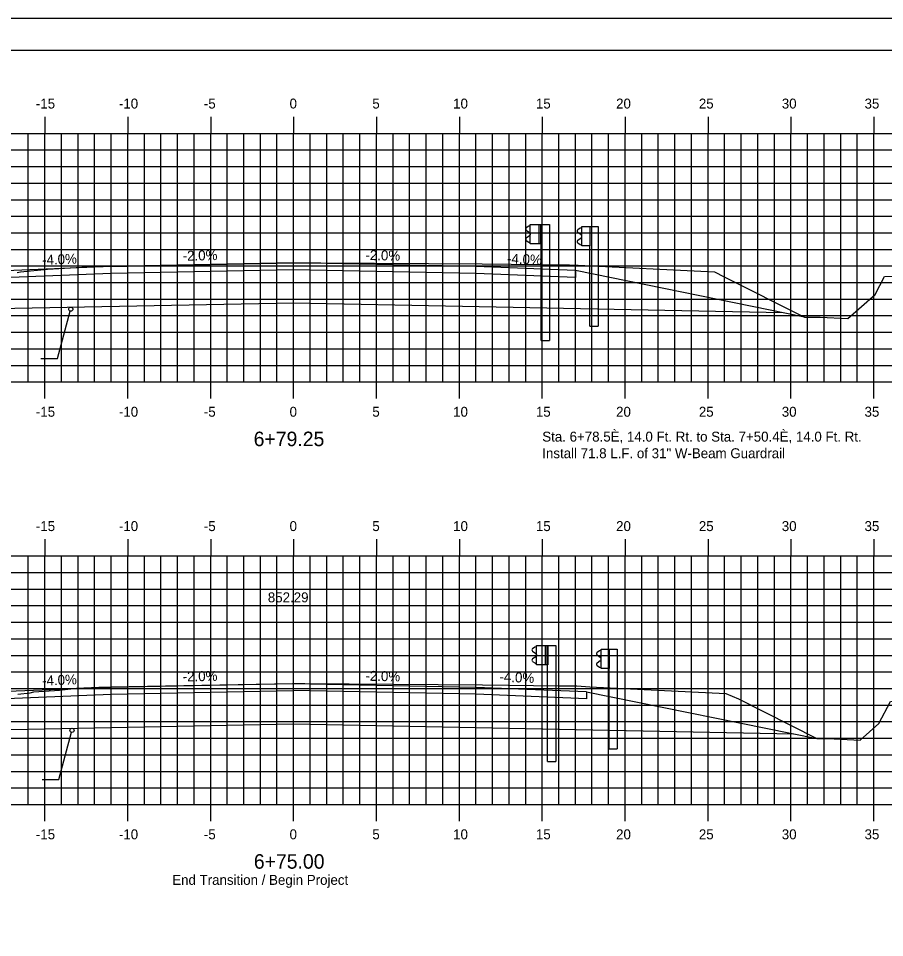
# Model space of a CAD drawing. Extents: x 2193811 to 2194294, y 863888 to 863998.
# Drawn here: x 2194016.6 to 2194068.9, y 863942.9 to 863998.4 of the extents above; entities that cross this region are included whole.
import ezdxf

# ---------------------------------------------------------------- set-up
doc = ezdxf.new("R2010")
doc.units = 0
for name, color, linetype in [('ANNOTATION', 7, 'Continuous'), ('BORDER', 7, 'Continuous'), ('D_Guardrail_Beam_Lt', 7, 'Continuous'), ('H_V ANNOTATION', 7, 'Continuous'), ('MAJOR', 7, 'Continuous'), ('MINOR', 7, 'Continuous'), ('PLOT BOUNDARY', 7, 'Continuous'), ('S_Guardrail_Beam', 7, 'Continuous'), ('S_Roadway_Centerline', 7, 'Continuous'), ('S_Utilities_Pole_Power', 7, 'Continuous'), ('TEMPLATE', 7, 'Continuous')]:
    doc.layers.add(name, color=color, linetype=linetype)

msp = doc.modelspace()

# ---------------------------------------------------------------- linework, layer by layer
at = {"layer": 'ANNOTATION'}
for points in [[(2194017.995, 863977.865), (2194018.995, 863977.865), (2194019.759, 863980.719)], [(2194018.072, 863952.447), (2194019.072, 863952.447), (2194019.836, 863955.301)]]:
    msp.add_lwpolyline(points, dxfattribs=at)
at = {"layer": 'BORDER'}
msp.add_lwpolyline([(2193958.23, 863891.446), (2194118.23, 863891.446), (2194118.23, 863996.446), (2193958.23, 863996.446)], close=True, dxfattribs=at)
at = {"layer": 'D_Guardrail_Beam_Lt'}
for p, q in [((2194047.5, 863985.869), (2194047.426, 863985.855)), ((2194047.5, 863985.952), (2194048.188, 863985.952)), ((2194047.5, 863984.786), (2194047.5, 863985.952)), ((2194048.021, 863985.952), (2194048.021, 863984.786)), ((2194048.125, 863985.952), (2194048.125, 863984.786)), ((2194048.188, 863985.952), (2194048.659, 863985.952)), ((2194048.188, 863985.952), (2194048.188, 863984.786)), ((2194048.659, 863985.952), (2194048.659, 863978.952)), ((2194047.411, 863985.848), (2194047.267, 863985.748)), ((2194047.267, 863985.605), (2194047.462, 863985.469)), ((2194047.496, 863985.404), (2194047.496, 863985.334)), ((2194047.462, 863985.27), (2194047.267, 863985.133)), ((2194047.267, 863984.99), (2194047.411, 863984.89)), ((2194047.426, 863984.884), (2194047.5, 863984.869)), ((2194048.188, 863984.786), (2194047.5, 863984.786)), ((2194048.167, 863978.952), (2194048.167, 863984.786)), ((2194048.167, 863978.952), (2194048.659, 863978.952)), ((2194047.791, 863960.443), (2194047.647, 863960.343)), ((2194047.88, 863960.464), (2194047.806, 863960.449)), ((2194047.88, 863960.547), (2194048.568, 863960.547)), ((2194047.88, 863959.381), (2194047.88, 863960.547)), ((2194048.401, 863960.547), (2194048.401, 863959.381)), ((2194048.505, 863960.547), (2194048.505, 863959.381)), ((2194048.568, 863960.547), (2194049.039, 863960.547)), ((2194048.568, 863960.547), (2194048.568, 863959.381)), ((2194049.039, 863960.547), (2194049.039, 863953.547)), ((2194047.647, 863960.2), (2194047.842, 863960.063)), ((2194047.842, 863959.864), (2194047.647, 863959.728)), ((2194047.876, 863959.999), (2194047.876, 863959.929)), ((2194047.647, 863959.585), (2194047.791, 863959.485)), ((2194047.806, 863959.478), (2194047.88, 863959.464)), ((2194048.568, 863959.381), (2194047.88, 863959.381)), ((2194048.547, 863953.547), (2194048.547, 863959.381)), ((2194048.547, 863953.547), (2194049.039, 863953.547))]:
    msp.add_line(p, q, dxfattribs=at)
for centre, major_axis, start_param, end_param in [((2194047.434, 863985.814), (-0.0417, 0), 4.907132, 5.323254), ((2194047.317, 863985.676), (-0.0877, 0), 5.323254, 7.243116), ((2194047.417, 863985.404), (0.0789, 0), 0, 0.959931), ((2194047.417, 863985.334), (0.0789, 0), 5.323254, 6.283185), ((2194047.317, 863985.062), (-0.0877, 0), 5.323254, 7.243116), ((2194047.434, 863984.924), (-0.0417, 0), 0.959931, 1.376053), ((2194047.697, 863960.271), (-0.0877, 0), 5.323254, 7.243116), ((2194047.814, 863960.409), (-0.0417, 0), 4.907132, 5.323254), ((2194047.797, 863959.999), (0.0789, 0), 0, 0.959931), ((2194047.797, 863959.929), (0.0789, 0), 5.323254, 6.283185), ((2194047.697, 863959.657), (-0.0877, 0), 5.323254, 7.243116), ((2194047.814, 863959.519), (-0.0417, 0), 0.959931, 1.376053)]:
    msp.add_ellipse(centre, major_axis=major_axis, ratio=0.995501, start_param=start_param, end_param=end_param, dxfattribs=at)
at = {"layer": 'MAJOR'}
for p, q in [((2194018.23, 863992.448), (2194018.23, 863991.446)), ((2194023.23, 863992.448), (2194023.23, 863991.446)), ((2194028.23, 863992.448), (2194028.23, 863991.446)), ((2194033.23, 863992.448), (2194033.23, 863991.446)), ((2194038.23, 863992.448), (2194038.23, 863991.446)), ((2194043.23, 863992.448), (2194043.23, 863991.446)), ((2194048.23, 863992.448), (2194048.23, 863991.446)), ((2194053.23, 863992.448), (2194053.23, 863991.446)), ((2194058.23, 863992.448), (2194058.23, 863991.446)), ((2194063.23, 863992.448), (2194063.23, 863991.446)), ((2194068.23, 863992.448), (2194068.23, 863991.446)), ((2193963.23, 863991.446), (2194103.23, 863991.446)), ((2193963.23, 863991.446), (2194103.23, 863991.446)), ((2194018.23, 863976.446), (2194018.23, 863991.446)), ((2194023.23, 863976.446), (2194023.23, 863991.446)), ((2194028.23, 863976.446), (2194028.23, 863991.446)), ((2194033.23, 863976.446), (2194033.23, 863991.446)), ((2194038.23, 863976.446), (2194038.23, 863991.446)), ((2194043.23, 863976.446), (2194043.23, 863991.446)), ((2194048.23, 863976.446), (2194048.23, 863991.446)), ((2194053.23, 863976.446), (2194053.23, 863991.446)), ((2194058.23, 863976.446), (2194058.23, 863991.446)), ((2194063.23, 863976.446), (2194063.23, 863991.446)), ((2194068.23, 863976.446), (2194068.23, 863991.446)), ((2193963.23, 863986.446), (2194103.23, 863986.446)), ((2193963.23, 863981.446), (2194103.23, 863981.446)), ((2193963.23, 863976.446), (2194103.23, 863976.446)), ((2194018.23, 863975.444), (2194018.23, 863976.446)), ((2194023.23, 863975.444), (2194023.23, 863976.446)), ((2194028.23, 863975.444), (2194028.23, 863976.446)), ((2194033.23, 863975.444), (2194033.23, 863976.446)), ((2194038.23, 863975.444), (2194038.23, 863976.446)), ((2194043.23, 863975.444), (2194043.23, 863976.446)), ((2194048.23, 863975.444), (2194048.23, 863976.446)), ((2194053.23, 863975.444), (2194053.23, 863976.446)), ((2194058.23, 863975.444), (2194058.23, 863976.446)), ((2194063.23, 863975.444), (2194063.23, 863976.446)), ((2194068.23, 863975.444), (2194068.23, 863976.446)), ((2194018.23, 863966.948), (2194018.23, 863965.946)), ((2194023.23, 863966.948), (2194023.23, 863965.946)), ((2194028.23, 863966.948), (2194028.23, 863965.946)), ((2194033.23, 863966.948), (2194033.23, 863965.946)), ((2194038.23, 863966.948), (2194038.23, 863965.946)), ((2194043.23, 863966.948), (2194043.23, 863965.946)), ((2194048.23, 863966.948), (2194048.23, 863965.946)), ((2194053.23, 863966.948), (2194053.23, 863965.946)), ((2194058.23, 863966.948), (2194058.23, 863965.946)), ((2194063.23, 863966.948), (2194063.23, 863965.946)), ((2194068.23, 863966.948), (2194068.23, 863965.946)), ((2193963.23, 863965.946), (2194103.23, 863965.946)), ((2193963.23, 863965.946), (2194103.23, 863965.946)), ((2194018.23, 863950.946), (2194018.23, 863965.946)), ((2194023.23, 863950.946), (2194023.23, 863965.946)), ((2194028.23, 863950.946), (2194028.23, 863965.946)), ((2194033.23, 863950.946), (2194033.23, 863965.946)), ((2194038.23, 863950.946), (2194038.23, 863965.946)), ((2194043.23, 863950.946), (2194043.23, 863965.946)), ((2194048.23, 863950.946), (2194048.23, 863965.946)), ((2194053.23, 863950.946), (2194053.23, 863965.946)), ((2194058.23, 863950.946), (2194058.23, 863965.946)), ((2194063.23, 863950.946), (2194063.23, 863965.946)), ((2194068.23, 863950.946), (2194068.23, 863965.946)), ((2193963.23, 863960.946), (2194103.23, 863960.946)), ((2193963.23, 863955.946), (2194103.23, 863955.946)), ((2193963.23, 863950.946), (2194103.23, 863950.946)), ((2194018.23, 863949.944), (2194018.23, 863950.946)), ((2194023.23, 863949.944), (2194023.23, 863950.946)), ((2194028.23, 863949.944), (2194028.23, 863950.946)), ((2194033.23, 863949.944), (2194033.23, 863950.946)), ((2194038.23, 863949.944), (2194038.23, 863950.946)), ((2194043.23, 863949.944), (2194043.23, 863950.946)), ((2194048.23, 863949.944), (2194048.23, 863950.946)), ((2194053.23, 863949.944), (2194053.23, 863950.946)), ((2194058.23, 863949.944), (2194058.23, 863950.946)), ((2194063.23, 863949.944), (2194063.23, 863950.946)), ((2194068.23, 863949.944), (2194068.23, 863950.946))]:
    msp.add_line(p, q, dxfattribs=at)
at = {"layer": 'MINOR'}
for p, q in [((2194017.23, 863976.446), (2194017.23, 863991.446)), ((2194019.23, 863976.446), (2194019.23, 863991.446)), ((2194020.23, 863976.446), (2194020.23, 863991.446)), ((2194021.23, 863976.446), (2194021.23, 863991.446)), ((2194022.23, 863976.446), (2194022.23, 863991.446)), ((2194024.23, 863976.446), (2194024.23, 863991.446)), ((2194025.23, 863976.446), (2194025.23, 863991.446)), ((2194026.23, 863976.446), (2194026.23, 863991.446)), ((2194027.23, 863976.446), (2194027.23, 863991.446)), ((2194029.23, 863976.446), (2194029.23, 863991.446)), ((2194030.23, 863976.446), (2194030.23, 863991.446)), ((2194031.23, 863976.446), (2194031.23, 863991.446)), ((2194032.23, 863976.446), (2194032.23, 863991.446)), ((2194034.23, 863976.446), (2194034.23, 863991.446)), ((2194035.23, 863976.446), (2194035.23, 863991.446)), ((2194036.23, 863976.446), (2194036.23, 863991.446)), ((2194037.23, 863976.446), (2194037.23, 863991.446)), ((2194039.23, 863976.446), (2194039.23, 863991.446)), ((2194040.23, 863976.446), (2194040.23, 863991.446)), ((2194041.23, 863976.446), (2194041.23, 863991.446)), ((2194042.23, 863976.446), (2194042.23, 863991.446)), ((2194044.23, 863976.446), (2194044.23, 863991.446)), ((2194045.23, 863976.446), (2194045.23, 863991.446)), ((2194046.23, 863976.446), (2194046.23, 863991.446)), ((2194047.23, 863976.446), (2194047.23, 863991.446)), ((2194049.23, 863976.446), (2194049.23, 863991.446)), ((2194050.23, 863976.446), (2194050.23, 863991.446)), ((2194051.23, 863976.446), (2194051.23, 863991.446)), ((2194052.23, 863976.446), (2194052.23, 863991.446)), ((2194054.23, 863976.446), (2194054.23, 863991.446)), ((2194055.23, 863976.446), (2194055.23, 863991.446)), ((2194056.23, 863976.446), (2194056.23, 863991.446)), ((2194057.23, 863976.446), (2194057.23, 863991.446)), ((2194059.23, 863976.446), (2194059.23, 863991.446)), ((2194060.23, 863976.446), (2194060.23, 863991.446)), ((2194061.23, 863976.446), (2194061.23, 863991.446)), ((2194062.23, 863976.446), (2194062.23, 863991.446)), ((2194064.23, 863976.446), (2194064.23, 863991.446)), ((2194065.23, 863976.446), (2194065.23, 863991.446)), ((2194066.23, 863976.446), (2194066.23, 863991.446)), ((2194067.23, 863976.446), (2194067.23, 863991.446)), ((2193963.23, 863990.446), (2194103.23, 863990.446)), ((2193963.23, 863989.446), (2194103.23, 863989.446)), ((2193963.23, 863988.446), (2194103.23, 863988.446)), ((2193963.23, 863987.446), (2194103.23, 863987.446)), ((2193963.23, 863985.446), (2194103.23, 863985.446)), ((2193963.23, 863984.446), (2194103.23, 863984.446)), ((2193963.23, 863983.446), (2194103.23, 863983.446)), ((2193963.23, 863982.446), (2194103.23, 863982.446)), ((2193963.23, 863980.446), (2194103.23, 863980.446)), ((2193963.23, 863979.446), (2194103.23, 863979.446)), ((2193963.23, 863978.446), (2194103.23, 863978.446)), ((2193963.23, 863977.446), (2194103.23, 863977.446)), ((2194017.23, 863950.946), (2194017.23, 863965.946)), ((2194019.23, 863950.946), (2194019.23, 863965.946)), ((2194020.23, 863950.946), (2194020.23, 863965.946)), ((2194021.23, 863950.946), (2194021.23, 863965.946)), ((2194022.23, 863950.946), (2194022.23, 863965.946)), ((2194024.23, 863950.946), (2194024.23, 863965.946)), ((2194025.23, 863950.946), (2194025.23, 863965.946)), ((2194026.23, 863950.946), (2194026.23, 863965.946)), ((2194027.23, 863950.946), (2194027.23, 863965.946)), ((2194029.23, 863950.946), (2194029.23, 863965.946)), ((2194030.23, 863950.946), (2194030.23, 863965.946)), ((2194031.23, 863950.946), (2194031.23, 863965.946)), ((2194032.23, 863950.946), (2194032.23, 863965.946)), ((2194034.23, 863950.946), (2194034.23, 863965.946)), ((2194035.23, 863950.946), (2194035.23, 863965.946)), ((2194036.23, 863950.946), (2194036.23, 863965.946)), ((2194037.23, 863950.946), (2194037.23, 863965.946)), ((2194039.23, 863950.946), (2194039.23, 863965.946)), ((2194040.23, 863950.946), (2194040.23, 863965.946)), ((2194041.23, 863950.946), (2194041.23, 863965.946)), ((2194042.23, 863950.946), (2194042.23, 863965.946)), ((2194044.23, 863950.946), (2194044.23, 863965.946)), ((2194045.23, 863950.946), (2194045.23, 863965.946)), ((2194046.23, 863950.946), (2194046.23, 863965.946)), ((2194047.23, 863950.946), (2194047.23, 863965.946)), ((2194049.23, 863950.946), (2194049.23, 863965.946)), ((2194050.23, 863950.946), (2194050.23, 863965.946)), ((2194051.23, 863950.946), (2194051.23, 863965.946)), ((2194052.23, 863950.946), (2194052.23, 863965.946)), ((2194054.23, 863950.946), (2194054.23, 863965.946)), ((2194055.23, 863950.946), (2194055.23, 863965.946)), ((2194056.23, 863950.946), (2194056.23, 863965.946)), ((2194057.23, 863950.946), (2194057.23, 863965.946)), ((2194059.23, 863950.946), (2194059.23, 863965.946)), ((2194060.23, 863950.946), (2194060.23, 863965.946)), ((2194061.23, 863950.946), (2194061.23, 863965.946)), ((2194062.23, 863950.946), (2194062.23, 863965.946)), ((2194064.23, 863950.946), (2194064.23, 863965.946)), ((2194065.23, 863950.946), (2194065.23, 863965.946)), ((2194066.23, 863950.946), (2194066.23, 863965.946)), ((2194067.23, 863950.946), (2194067.23, 863965.946)), ((2193963.23, 863964.946), (2194103.23, 863964.946)), ((2193963.23, 863963.946), (2194103.23, 863963.946)), ((2193963.23, 863962.946), (2194103.23, 863962.946)), ((2193963.23, 863961.946), (2194103.23, 863961.946)), ((2193963.23, 863959.946), (2194103.23, 863959.946)), ((2193963.23, 863958.946), (2194103.23, 863958.946)), ((2193963.23, 863957.946), (2194103.23, 863957.946)), ((2193963.23, 863956.946), (2194103.23, 863956.946)), ((2193963.23, 863954.946), (2194103.23, 863954.946)), ((2193963.23, 863953.946), (2194103.23, 863953.946)), ((2193963.23, 863952.946), (2194103.23, 863952.946)), ((2193963.23, 863951.946), (2194103.23, 863951.946))]:
    msp.add_line(p, q, dxfattribs=at)
at = {"layer": 'PLOT BOUNDARY'}
msp.add_lwpolyline([(2193950.137, 863888.387), (2194120.137, 863888.387), (2194120.137, 863998.387), (2193950.137, 863998.387)], close=True, dxfattribs=at)
at = {"layer": 'S_Guardrail_Beam'}
for p, q in [((2194050.515, 863985.727), (2194050.372, 863985.627)), ((2194050.372, 863985.484), (2194050.567, 863985.347)), ((2194050.614, 863985.748), (2194050.532, 863985.733)), ((2194050.614, 863985.821), (2194051.104, 863985.821)), ((2194050.614, 863984.654), (2194050.614, 863985.821)), ((2194051.104, 863985.821), (2194051.595, 863985.821)), ((2194051.104, 863985.821), (2194051.104, 863984.654)), ((2194051.595, 863985.821), (2194051.595, 863979.821)), ((2194050.567, 863985.128), (2194050.372, 863984.991)), ((2194050.372, 863984.848), (2194050.515, 863984.748)), ((2194050.532, 863984.741), (2194050.614, 863984.727)), ((2194050.601, 863985.283), (2194050.601, 863985.192)), ((2194051.104, 863984.654), (2194050.614, 863984.654)), ((2194051.104, 863979.821), (2194051.104, 863984.654)), ((2194051.104, 863979.821), (2194051.595, 863979.821)), ((2194051.677, 863960.218), (2194051.533, 863960.118)), ((2194051.533, 863959.975), (2194051.729, 863959.839)), ((2194051.775, 863960.239), (2194051.693, 863960.225)), ((2194051.775, 863960.312), (2194052.265, 863960.312)), ((2194051.775, 863959.145), (2194051.775, 863960.312)), ((2194052.265, 863960.312), (2194052.757, 863960.312)), ((2194052.265, 863960.312), (2194052.265, 863959.145)), ((2194052.757, 863960.312), (2194052.757, 863954.312)), ((2194051.729, 863959.619), (2194051.533, 863959.483)), ((2194051.533, 863959.34), (2194051.677, 863959.24)), ((2194051.693, 863959.233), (2194051.775, 863959.218)), ((2194051.762, 863959.774), (2194051.762, 863959.683)), ((2194052.265, 863959.145), (2194051.775, 863959.145)), ((2194052.265, 863954.312), (2194052.265, 863959.145)), ((2194052.265, 863954.312), (2194052.757, 863954.312))]:
    msp.add_line(p, q, dxfattribs=at)
for centre, major_axis, start_param, end_param in [((2194050.422, 863985.555), (-0.0877, 0), 5.323254, 7.243116), ((2194050.539, 863985.693), (-0.0417, 0), 4.886922, 5.323254), ((2194050.522, 863985.283), (0.0789, 0), 0, 0.959931), ((2194050.422, 863984.92), (-0.0877, 0), 5.323254, 7.243116), ((2194050.539, 863984.782), (-0.0417, 0), 0.959931, 1.396263), ((2194050.522, 863985.192), (0.0789, 0), 5.323254, 6.283185), ((2194051.584, 863960.046), (-0.0877, 0), 5.323254, 7.243116), ((2194051.701, 863960.184), (-0.0417, 0), 4.886922, 5.323254), ((2194051.683, 863959.774), (0.0789, 0), 0, 0.959931), ((2194051.584, 863959.411), (-0.0877, 0), 5.323254, 7.243116), ((2194051.701, 863959.274), (-0.0417, 0), 0.959931, 1.396263), ((2194051.683, 863959.683), (0.0789, 0), 5.323254, 6.283185)]:
    msp.add_ellipse(centre, major_axis=major_axis, ratio=0.995501, start_param=start_param, end_param=end_param, dxfattribs=at)
at = {"layer": 'S_Roadway_Centerline'}
for points in [[(2194016.557, 863983.055), (2194016.765, 863983.092), (2194018.378, 863983.255), (2194021.489, 863983.44), (2194023.229, 863983.455), (2194033.175, 863983.634), (2194034.877, 863983.638), (2194044.611, 863983.565), (2194049.88, 863983.514), (2194050.405, 863983.486), (2194058.621, 863983.086), (2194059.206, 863982.798), (2194064.04, 863980.357), (2194065.001, 863980.36), (2194066.666, 863980.278), (2194068.305, 863981.729), (2194068.874, 863982.809), (2194096.108, 863983.744), (2194097.763, 863983.85), (2194103.23, 863983.988)], [(2194016.591, 863957.61), (2194017.347, 863957.685), (2194017.573, 863957.739), (2194019.11, 863957.853), (2194020.143, 863957.957), (2194021.474, 863958.036), (2194022.219, 863958.043), (2194033.171, 863958.24), (2194033.91, 863958.242), (2194044.627, 863958.16), (2194049.245, 863958.116), (2194050.311, 863958.103), (2194051.1, 863958.054), (2194059.304, 863957.643), (2194060.075, 863957.316), (2194064.798, 863954.93), (2194065.457, 863954.932), (2194067.414, 863954.836), (2194068.532, 863955.825), (2194069.241, 863957.171), (2194091.052, 863957.92), (2194098.542, 863958.402), (2194103.23, 863958.52)]]:
    msp.add_lwpolyline(points, dxfattribs=at)
at = {"layer": 'S_Utilities_Pole_Power'}
for centre in [(2194019.792, 863980.839), (2194019.869, 863955.421)]:
    msp.add_circle(centre, 0.125, dxfattribs=at)
at = {"layer": 'TEMPLATE'}
for p, q in [((2194022.23, 863983.406), (2194014.139, 863983.082)), ((2194022.23, 863983.406), (2194033.23, 863983.626)), ((2194033.23, 863983.626), (2194022.23, 863983.406)), ((2194033.23, 863983.209), (2194022.23, 863982.989)), ((2194044.23, 863983.406), (2194033.23, 863983.626)), ((2194044.23, 863982.989), (2194033.23, 863983.209)), ((2194050.23, 863983.166), (2194044.23, 863983.406)), ((2194064.04, 863980.357), (2194050.23, 863983.166)), ((2194033.23, 863981.209), (2194006.648, 863980.677)), ((2194062.753, 863980.619), (2194033.23, 863981.209)), ((2194022.23, 863957.599), (2194033.23, 863957.819)), ((2194044.23, 863957.599), (2194033.23, 863957.819)), ((2194050.895, 863957.749), (2194064.798, 863954.93))]:
    msp.add_line(p, q, dxfattribs=at)
for points in [[(2194022.23, 863982.989), (2194014.139, 863982.665), (2194014.139, 863983.082)], [(2194050.23, 863983.166), (2194050.23, 863982.749), (2194044.23, 863982.989)], [(2194050.895, 863957.749), (2194044.23, 863958.016), (2194033.23, 863958.236), (2194022.23, 863958.016), (2194014.902, 863957.723)], [(2194014.902, 863957.723), (2194014.902, 863957.306), (2194022.23, 863957.599)], [(2194050.895, 863957.749), (2194050.895, 863957.332), (2194044.23, 863957.599)], [(2194006.042, 863955.275), (2194022.23, 863955.599), (2194033.23, 863955.819), (2194044.23, 863955.599), (2194063.388, 863955.216)]]:
    msp.add_lwpolyline(points, dxfattribs=at)

# ---------------------------------------------------------------- texts
at = {"layer": 'ANNOTATION'}
for s, rotation, p in [('-2.0%', 1.1458, (2194026.547, 863983.759)), ('-2.0%', 358.8542, (2194037.558, 863983.806)), ('-4.0%', 2.2906, (2194018.075, 863983.507)), ('-4.0%', 357.7094, (2194046.096, 863983.598)), ('-4.0%', 2.2906, (2194018.075, 863958.117)), ('-2.0%', 1.1458, (2194026.547, 863958.369)), ('-2.0%', 358.8542, (2194037.558, 863958.416)), ('-4.0%', 357.7094, (2194045.64, 863958.36))]:
    msp.add_text(s, height=0.6, rotation=rotation, dxfattribs=at).set_placement(p)
for s, p in [('Sta. 6+78.5È, 14.0 Ft. Rt. to Sta. 7+50.4È, 14.0 Ft. Rt.', (2194048.23, 863972.846)), ('Install 71.8 L.F. of 31" W-Beam Guardrail', (2194048.23, 863971.844)), ('852.29', (2194031.678, 863963.146)), ('End Transition / Begin Project', (2194025.91, 863946.096))]:
    msp.add_text(s, height=0.6, dxfattribs=at).set_placement(p)
at = {"layer": 'H_V ANNOTATION'}
for s, height, p in [('-15', 0.6, (2194017.687, 863992.946)), ('-10', 0.6, (2194022.695, 863992.946)), ('-5', 0.6, (2194027.82, 863992.946)), ('0', 0.6, (2194032.989, 863992.946)), ('5', 0.6, (2194037.981, 863992.946)), ('10', 0.6, (2194042.855, 863992.946)), ('15', 0.6, (2194047.847, 863992.946)), ('20', 0.6, (2194052.684, 863992.946)), ('25', 0.6, (2194057.676, 863992.946)), ('30', 0.6, (2194062.678, 863992.946)), ('35', 0.6, (2194067.67, 863992.946)), ('-15', 0.6, (2194017.687, 863974.346)), ('-10', 0.6, (2194022.695, 863974.346)), ('-5', 0.6, (2194027.82, 863974.346)), ('0', 0.6, (2194032.989, 863974.346)), ('5', 0.6, (2194037.981, 863974.346)), ('10', 0.6, (2194042.855, 863974.346)), ('15', 0.6, (2194047.847, 863974.346)), ('20', 0.6, (2194052.684, 863974.346)), ('25', 0.6, (2194057.676, 863974.346)), ('30', 0.6, (2194062.678, 863974.346)), ('35', 0.6, (2194067.67, 863974.346)), ('6+79.25', 0.875, (2194030.823, 863972.571)), ('-15', 0.6, (2194017.687, 863967.446)), ('-10', 0.6, (2194022.695, 863967.446)), ('-5', 0.6, (2194027.82, 863967.446)), ('0', 0.6, (2194032.989, 863967.446)), ('5', 0.6, (2194037.981, 863967.446)), ('10', 0.6, (2194042.855, 863967.446)), ('15', 0.6, (2194047.847, 863967.446)), ('20', 0.6, (2194052.684, 863967.446)), ('25', 0.6, (2194057.676, 863967.446)), ('30', 0.6, (2194062.678, 863967.446)), ('35', 0.6, (2194067.67, 863967.446)), ('-15', 0.6, (2194017.687, 863948.846)), ('-10', 0.6, (2194022.695, 863948.846)), ('-5', 0.6, (2194027.82, 863948.846)), ('0', 0.6, (2194032.989, 863948.846)), ('5', 0.6, (2194037.981, 863948.846)), ('10', 0.6, (2194042.855, 863948.846)), ('15', 0.6, (2194047.847, 863948.846)), ('20', 0.6, (2194052.684, 863948.846)), ('25', 0.6, (2194057.676, 863948.846)), ('30', 0.6, (2194062.678, 863948.846)), ('35', 0.6, (2194067.67, 863948.846)), ('6+75.00', 0.875, (2194030.834, 863947.071))]:
    msp.add_text(s, height=height, dxfattribs=at).set_placement(p)

doc.saveas('drawing.dxf')
